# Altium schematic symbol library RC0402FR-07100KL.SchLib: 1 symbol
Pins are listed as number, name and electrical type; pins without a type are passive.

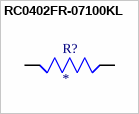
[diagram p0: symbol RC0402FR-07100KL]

## RC0402FR-07100KL
designator R?
100 kOhms Â±1% 0.063W, 1/16W Chip Resistor 0402 (1005 Metric) Moisture Resistant Thick Film; MF: Yageo; MP: RC0402FR-07100KL
footprint RESC1005X40
pins: 1, 2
